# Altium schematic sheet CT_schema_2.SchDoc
size 297 x 247 mm
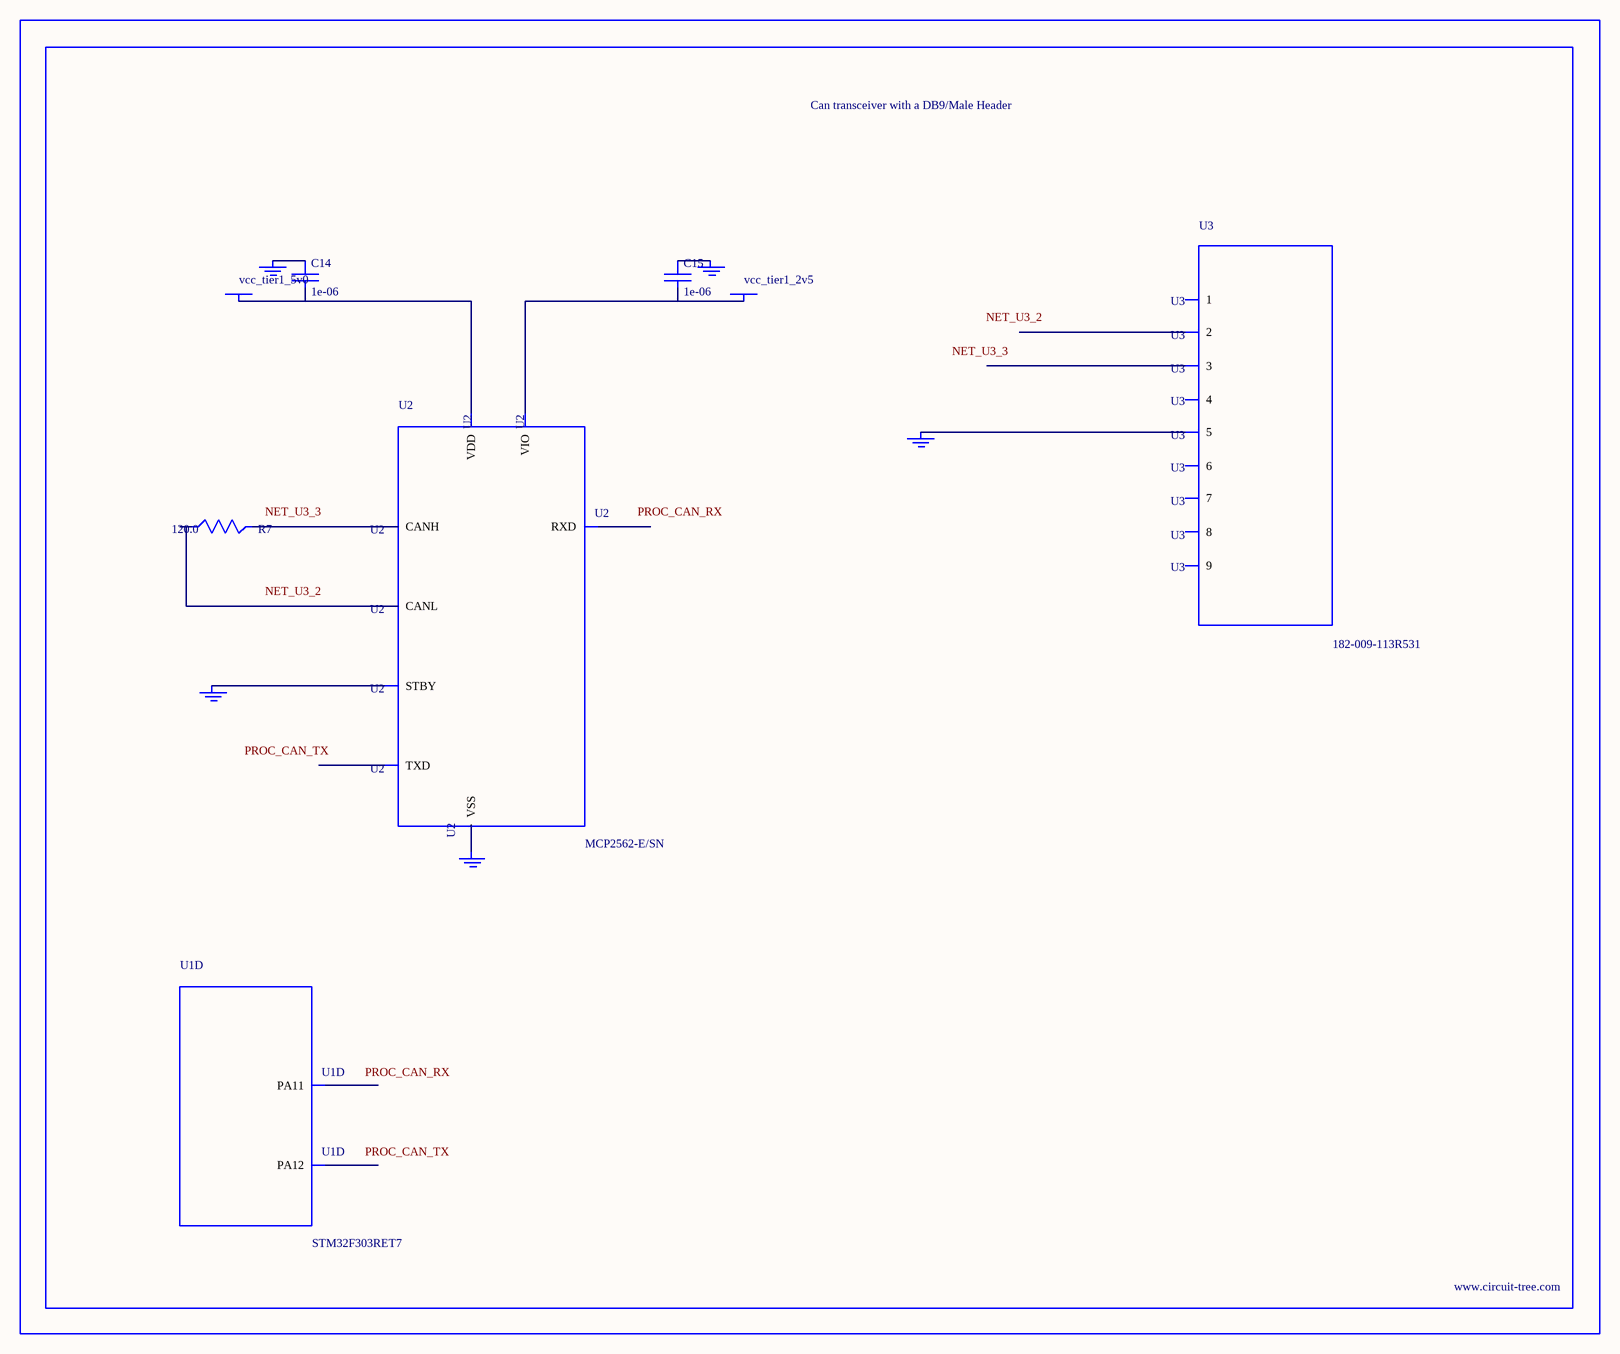
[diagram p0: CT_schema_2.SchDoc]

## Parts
BORDER1  (no value)
C14  1e-06  [C0603]
C15  1e-06  [C0603]
GND_INSTANCE_1_0  (no value)
GND_INSTANCE_1_1  (no value)
GND_INSTANCE_1_2  (no value)
GND_INSTANCE_1_3  (no value)
GND_INSTANCE_1_4  (no value)
POWER_INSTANCE_1_0  vcc_tier1_5v0
POWER_INSTANCE_1_1  vcc_tier1_2v5
R7  120.0  [R0603]
U1  STM32F303RET7  [LQFP64]  (part D of 6)
U2  MCP2562-E/SN  [SOIC-8]
U3  182-009-113R531  [182-009-MALE]

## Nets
NetC14_1: C14.1 GND_INSTANCE_1_0.0(GND)
NetC14_2: C14.2 POWER_INSTANCE_1_0.0(PWR) U2.3(VDD)
NetC15_1: C15.1 GND_INSTANCE_1_1.0(GND)
NetC15_2: C15.2 POWER_INSTANCE_1_1.0(PWR) U2.5(VIO)
NetGND_INSTANCE_1_2_0: GND_INSTANCE_1_2.0(GND) U2.8(STBY)
NetGND_INSTANCE_1_3_0: GND_INSTANCE_1_3.0(GND) U2.2(VSS)
NetGND_INSTANCE_1_4_0: GND_INSTANCE_1_4.0(GND) U3.5
NetR7_1: R7.1 U2.6(CANL)
NetR7_2: R7.2 U2.7(CANH)

Not connected (* = marked no-connect by the designer): U1 44(PA11) 45(PA12); U2 1(TXD) 4(RXD); U3 1 2 3 4 6 7 8 9

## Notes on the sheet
- Labels drawn without touching a wire or pin: NET_U3_2, NET_U3_3, PROC_CAN_RX, PROC_CAN_TX

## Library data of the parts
BORDER1 = BORDER_PAGE1
C14 C15 = C0603C105K3RACTU
GND_INSTANCE_1_0-GND_INSTANCE_1_4 = GND
POWER_INSTANCE_1_0 POWER_INSTANCE_1_1 = PWR
R7 = RC0603JR-07120RL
